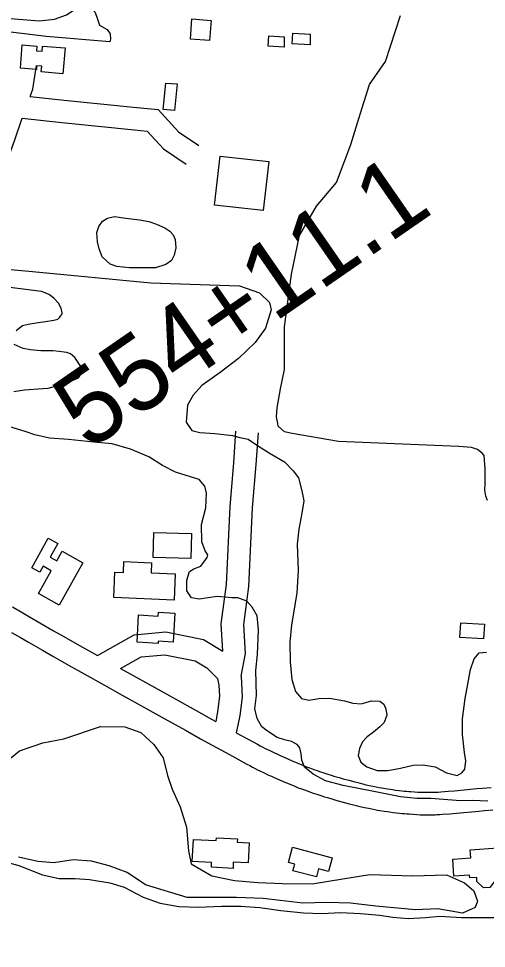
# Model space of a CAD drawing. Extents: x 3715084 to 3753216, y 488173 to 513963.
# Drawn here: x 3736153 to 3736776, y 500239 to 501479 of the extents above; entities that cross this region are included whole.
import ezdxf

# ---------------------------------------------------------------- set-up
doc = ezdxf.new("R2010")
doc.units = 0
for name, color, linetype in [('V-BLDG-OTLN', 7, 'Continuous'), ('V-ROAD-CNTR', 7, 'Continuous'), ('V-SITE-VEGE', 7, 'Continuous'), ('V-SURV-IDEN', 7, 'Continuous'), ('V-TOPO-SHOR', 7, 'Continuous')]:
    doc.layers.add(name, color=color, linetype=linetype)

msp = doc.modelspace()

# ---------------------------------------------------------------- linework, layer by layer
at = {"layer": 'V-BLDG-OTLN'}
for points in [[(3736409.2, 501476.5), (3736407.3, 501449.5), (3736381.7, 501451.3), (3736383.6, 501478.4)], [(3736506.8, 501441), (3736485.4, 501442.2), (3736486.1, 501455.8), (3736506.7, 501454.7)], [(3736541.1, 501443.9), (3736517.3, 501445.1), (3736518, 501459.3), (3736541.4, 501458.1)], [(3736184.7, 501442.3), (3736214.9, 501439.7), (3736212, 501405.3), (3736183.1, 501407.8), (3736183.7, 501415.3), (3736176.9, 501415.9), (3736176.5, 501411.2), (3736155.2, 501413), (3736157.8, 501443.7), (3736177, 501442.1), (3736176.5, 501436.1), (3736184.1, 501435.4)], [(3736364.1, 501391.7), (3736360.6, 501356.4), (3736345.5, 501357.8), (3736349, 501392.9)], [(3736478.8, 501223.1), (3736414, 501230.3), (3736421.2, 501295.5), (3736486, 501288.3)], [(3736333.2, 500793.8), (3736383.4, 500792.5), (3736382.5, 500759.1), (3736332.3, 500760.4)], [(3736238.5, 500753.3), (3736206.9, 500696.6), (3736179.2, 500712.1), (3736196.2, 500742.6), (3736185.5, 500748.6), (3736181.1, 500740.6), (3736170.4, 500746.5), (3736192.4, 500786), (3736205.1, 500778.9), (3736195, 500760.8), (3736203.6, 500756), (3736210.8, 500768.7)], [(3736329.3, 500739.7), (3736361.5, 500738.4), (3736360.1, 500703.6), (3736279.7, 500706.8), (3736281.1, 500740.8), (3736292.6, 500740.3), (3736293.2, 500754.8), (3736329.8, 500753.3)], [(3736360.8, 500686.3), (3736358.9, 500647.6), (3736338.9, 500648.7), (3736338.7, 500645.8), (3736310.6, 500647.2), (3736312.4, 500683.7), (3736339, 500682.3), (3736339.2, 500687.4)], [(3736742, 500673.3), (3736773.5, 500671.3), (3736772.3, 500651.9), (3736740.8, 500653.8)], [(3736460, 500380), (3736458.7, 500353), (3736438.9, 500353.9), (3736438.5, 500345.8), (3736409.7, 500347.2), (3736410, 500353.6), (3736384.3, 500354.9), (3736385.8, 500384.3), (3736416.2, 500382.9), (3736416.4, 500386.6), (3736444.4, 500385.3), (3736444.2, 500380.8)], [(3736517.9, 500374.2), (3736570.7, 500360), (3736565.8, 500341.5), (3736552.5, 500345.1), (3736549.6, 500334.3), (3736518.4, 500342.7), (3736520.7, 500351.3), (3736512.4, 500353.5)], [(3736827.9, 500337.2), (3736787.3, 500334.6), (3736787.6, 500329.5), (3736780.5, 500320.5), (3736772.2, 500319.8), (3736763.5, 500328.4), (3736763.3, 500333.6), (3736754, 500333), (3736753.7, 500336.6), (3736732.6, 500335.2), (3736731.2, 500358.1), (3736755.2, 500359.7), (3736754.5, 500370.7), (3736791.4, 500373), (3736792.1, 500361.4), (3736826.2, 500363.5), (3736826.4, 500360.4), (3736838.4, 500361.2), (3736839.8, 500339.8), (3736827.8, 500339)]]:
    msp.add_lwpolyline(points, close=True, dxfattribs=at)
at = {"layer": 'V-ROAD-CNTR'}
for points in [[(3736168.2, 501375.2), (3736171.8, 501384.7), (3736176.5, 501416.5)], [(3736168.2, 501375.2), (3736213.4, 501370.3), (3736310.5, 501360.5), (3736338.7, 501357.5), (3736365.7, 501328.1), (3736392.9, 501309.6)], [(3736047.3, 501279.8), (3736088, 501278.7), (3736133.7, 501278), (3736148, 501317.2), (3736157.5, 501346.2)], [(3736157.5, 501346.2), (3736210.3, 501340.4), (3736307.4, 501330.7), (3736324.3, 501328.9), (3736346, 501305.2), (3736376.1, 501284.8)], [(3736424.9, 500635.2), (3736422.6, 500671.9), (3736429.7, 500724.4), (3736434.6, 500828.5), (3736439.4, 500886.7), (3736442.4, 500928.7)], [(3736449.3, 500602.1), (3736455.2, 500632.1), (3736452.8, 500670.8), (3736459.6, 500721.7), (3736464.5, 500826.6), (3736469.3, 500884.4), (3736472.4, 500926.5)], [(3736144.8, 500694.4), (3736158.5, 500686.4), (3736170.5, 500679.4), (3736181, 500673.4), (3736199.5, 500662.7), (3736213.3, 500654.8), (3736234.2, 500643), (3736257.8, 500629.7)], [(3736143.4, 500660.5), (3736155.5, 500653.5), (3736166.1, 500647.4), (3736184.6, 500636.7), (3736198.5, 500628.8), (3736219.4, 500616.9), (3736240.3, 500605.1), (3736267.3, 500589.9), (3736290.9, 500576.7), (3736311.6, 500565.1), (3736347.8, 500545), (3736375, 500529.9), (3736395.4, 500518.6), (3736410.7, 500510.1), (3736433.7, 500497.5), (3736456.8, 500484.9), (3736460.7, 500482.8), (3736464.4, 500480.8), (3736467.9, 500479), (3736471.2, 500477.4), (3736474.3, 500475.9), (3736480, 500473.1), (3736485.1, 500470.7), (3736489.6, 500468.6), (3736493.5, 500466.9), (3736500.3, 500463.9), (3736505.5, 500461.7), (3736513.3, 500458.4), (3736521, 500455.2), (3736525.5, 500453.4), (3736529.7, 500451.8), (3736533.6, 500450.4), (3736537.4, 500449), (3736540.8, 500447.8), (3736544.1, 500446.6), (3736550.2, 500444.6), (3736555.6, 500442.9), (3736560.2, 500441.4)], [(3736257.8, 500629.7), (3736307, 500657), (3736349.1, 500661), (3736399, 500651), (3736424.9, 500635.2)], [(3736288.5, 500612.4), (3736316, 500627.8), (3736347.5, 500630.7), (3736387.9, 500622.6), (3736403.5, 500613.1), (3736418, 500599), (3736419.8, 500590.1), (3736420.5, 500575.2), (3736417.9, 500554.4), (3736415.4, 500541.8)], [(3736288.5, 500612.4), (3736305.6, 500602.9), (3736326.2, 500591.3), (3736362.4, 500571.2), (3736389.5, 500556.1), (3736409.9, 500544.9), (3736415.4, 500541.8)], [(3736449.3, 500602.1), (3736450.6, 500574), (3736447.5, 500549.6), (3736444.9, 500536.7), (3736442.8, 500526.7)], [(3736442.8, 500526.7), (3736471.1, 500511.3), (3736474.8, 500509.3), (3736478.2, 500507.5), (3736481.5, 500505.8), (3736484.6, 500504.2), (3736487.4, 500502.8), (3736492.9, 500500.2), (3736497.7, 500497.9), (3736502, 500496), (3736505.7, 500494.3), (3736512.3, 500491.4), (3736517.2, 500489.3), (3736524.7, 500486.1), (3736532.3, 500483), (3736536.4, 500481.4), (3736540.4, 500479.9), (3736544, 500478.5), (3736547.5, 500477.2), (3736550.7, 500476.1), (3736553.8, 500475), (3736559.6, 500473.1), (3736564.6, 500471.5), (3736569.2, 500470)], [(3736569.1, 500470.1), (3736573, 500468.9), (3736579.9, 500466.8), (3736585.1, 500465.3), (3736593, 500463.2), (3736600.9, 500461), (3736604.6, 500460.1), (3736608.1, 500459.2), (3736611.3, 500458.4), (3736614.3, 500457.7), (3736620, 500456.4), (3736624.9, 500455.3), (3736629.3, 500454.4), (3736633.1, 500453.7), (3736636.4, 500453.1), (3736639.3, 500452.6), (3736644.4, 500451.7), (3736648.2, 500451.2), (3736651.1, 500450.8), (3736655.4, 500450.2), (3736659.8, 500449.7), (3736663.3, 500449.3), (3736666.6, 500448.9), (3736669.7, 500448.6), (3736672.6, 500448.4), (3736675.3, 500448.2), (3736680.4, 500447.8), (3736684.8, 500447.6), (3736688.7, 500447.4), (3736692, 500447.3), (3736695, 500447.2), (3736697.5, 500447.2), (3736699.7, 500447.2), (3736703.7, 500447.3), (3736706.6, 500447.4), (3736708.7, 500447.4), (3736712, 500447.6), (3736715.3, 500447.8), (3736724.9, 500448.6), (3736733.4, 500449.4), (3736763.4, 500452.1), (3736770.9, 500452.8), (3736782.2, 500453.8)], [(3736560.3, 500441.4), (3736564.4, 500440.1), (3736571.6, 500438), (3736577, 500436.5), (3736585.1, 500434.2), (3736593.3, 500432), (3736597.2, 500431), (3736600.8, 500430.1), (3736604.2, 500429.3), (3736607.5, 500428.5), (3736613.5, 500427.1), (3736618.8, 500426), (3736623.4, 500425), (3736627.5, 500424.2), (3736631.1, 500423.6), (3736634.2, 500423), (3736639.7, 500422.1), (3736643.9, 500421.5), (3736647, 500421), (3736651.7, 500420.4), (3736656.4, 500419.9), (3736660.2, 500419.4), (3736663.7, 500419.1), (3736667, 500418.8), (3736670.1, 500418.5), (3736673, 500418.3), (3736678.5, 500417.9), (3736683.3, 500417.6), (3736687.6, 500417.4), (3736691.3, 500417.3), (3736694.5, 500417.2), (3736697.4, 500417.2), (3736699.9, 500417.2), (3736704.3, 500417.3), (3736707.6, 500417.4), (3736710.1, 500417.5), (3736713.8, 500417.7), (3736717.5, 500417.9), (3736727.5, 500418.7), (3736736.1, 500419.5), (3736766.1, 500422.2), (3736773.6, 500422.9), (3736784.7, 500423.9)]]:
    msp.add_lwpolyline(points, dxfattribs=at)
msp.add_spline([(3733715.6, 498954.1), (3733927.4, 498985.4), (3734149, 499017.4), (3734317.1, 499039.2), (3734452.5, 499051), (3734616.6, 499062.1), (3734803.5, 499064.4), (3734911.8, 499064.8), (3735132.1, 499070), (3735323.3, 499078.4), (3735505.8, 499097.1), (3735898.1, 499142.6), (3736237.2, 499184.4), (3736547.4, 499225.5), (3736808.2, 499257.6), (3736976.4, 499281.2), (3737080, 499296.5), (3737176, 499320.7), (3737240, 499343.3), (3737319.4, 499377.9), (3737388.9, 499415.8), (3737461.6, 499455.9), (3737533.7, 499510.1), (3737613.7, 499584.1), (3737686.3, 499661.4), (3737745.2, 499744.2), (3737793.2, 499828.8), (3737831, 499907.6), (3737863.3, 499993.7), (3737884.5, 500070), (3737902, 500150.4), (3737918.8, 500240.6), (3737947.8, 500405.1), (3737975.6, 500525.4)], degree=3, dxfattribs=at)
at = {"layer": 'V-SITE-VEGE'}
msp.add_lwpolyline([(3736033.3, 501474.3), (3736029.3, 501474.9), (3736026.4, 501475.4), (3736022.3, 501479.5), (3736020.6, 501483), (3736021.7, 501487.6), (3736028.1, 501489.9), (3736097.8, 501482.4), (3736180.2, 501476), (3736200.5, 501478.3), (3736216.7, 501484.1), (3736229.5, 501492.2), (3736239.4, 501494.5), (3736248.1, 501494.5), (3736254.4, 501488.1), (3736256.8, 501482.3), (3736260.8, 501470.1), (3736270.7, 501464.3), (3736274.7, 501458.5), (3736275.3, 501451.6), (3736274.2, 501448.1), (3736189.4, 501455.1)], close=True, dxfattribs=at)
for points in [[(3736777.4, 500836.2), (3736775.1, 500842.1), (3736773.9, 500850.3), (3736774.5, 500859.1), (3736774.5, 500878.5), (3736773.3, 500896.1), (3736770.4, 500899.6), (3736764, 500904.3), (3736756.3, 500907.2), (3736739.3, 500908.4), (3736579.1, 500914.9), (3736517.5, 500925.5), (3736506.9, 500927.9), (3736498.7, 500935.5), (3736498.1, 500939), (3736496.3, 500947.8), (3736497.5, 500960.1), (3736501.6, 500985.4), (3736506.9, 501011), (3736506.9, 501068), (3736516.6, 501138.1), (3736526.9, 501189.6), (3736549.6, 501228.7), (3736576.4, 501260.3), (3736595.6, 501311.2), (3736605.9, 501345.5), (3736620.4, 501390.8), (3736641.7, 501421.8), (3736661.6, 501482.9)], [(3736024.5, 501155.1), (3736171.3, 501141.7), (3736329.2, 501126.6), (3736447, 501122.5), (3736473.7, 501113.2), (3736487, 501100.4), (3736489.3, 501090.5), (3736481.8, 501066.2), (3736467.8, 501047), (3736445.8, 501025.6), (3736421.4, 501007), (3736397, 500989.6), (3736385.4, 500976.8), (3736377.8, 500963.5), (3736376.1, 500940.9), (3736383.6, 500929.8), (3736394.1, 500926.9), (3736414.4, 500925.8)], [(3736149.8, 501062.8), (3736158, 501069.8), (3736165.5, 501071.5), (3736178.8, 501073.8), (3736188.7, 501075), (3736199.7, 501076.7), (3736205, 501077.9), (3736207.9, 501080.8), (3736210.8, 501085.4), (3736210.8, 501086.6), (3736209.6, 501093), (3736206.1, 501099.3), (3736199.8, 501106.3), (3736193.9, 501110.4), (3736188.1, 501113.3), (3736183.5, 501115), (3736137.7, 501120.8)], [(3736146.3, 500981.6), (3736160.8, 500983.9), (3736178.8, 500985), (3736192.2, 500986.2), (3736216.5, 500992.6), (3736232.8, 501000.1), (3736237.4, 501007.1), (3736237.4, 501012.3), (3736227.6, 501026.8), (3736221.8, 501032), (3736217.1, 501033.8), (3736213.7, 501034.3), (3736206.7, 501034.9), (3736198.6, 501036.1), (3736182.3, 501036.1), (3736168.4, 501037.3), (3736159.1, 501039), (3736146.9, 501044.2)], [(3736497.2, 500520.1), (3736484.5, 500528.8), (3736476.9, 500534.6), (3736470.5, 500545.6), (3736467.6, 500558.4), (3736470, 500576.4), (3736468.8, 500609.5), (3736471.2, 500630.9), (3736472.3, 500664), (3736470.6, 500682.6), (3736464.2, 500694.2), (3736456.7, 500702.3), (3736445.1, 500706.4), (3736436.9, 500706.4), (3736417.2, 500708.1), (3736393.4, 500704.7), (3736383, 500706.4), (3736377.2, 500715.7), (3736377.2, 500730.2), (3736380.7, 500741.8), (3736386.5, 500745.3), (3736395.8, 500748.8), (3736403.9, 500760.4), (3736405, 500763.9), (3736401.6, 500769.1), (3736396.9, 500781.3), (3736396.4, 500804.5), (3736402.2, 500826.5), (3736403.3, 500846.3), (3736401, 500855.5), (3736393.5, 500864.2), (3736381.9, 500867.7), (3736362.1, 500874.1), (3736344.7, 500882.8), (3736326.2, 500894.4), (3736301.8, 500904.9), (3736277.4, 500911.9), (3736253.1, 500914.2), (3736219.4, 500917.7), (3736193.9, 500919.5), (3736174.7, 500924.1), (3736161.4, 500928.2), (3736141.1, 500934.6)], [(3736414.4, 500925.8), (3736437.6, 500922.8), (3736447.5, 500920.5), (3736458.5, 500918.2), (3736472.4, 500908.9), (3736488.1, 500899), (3736507.2, 500888), (3736518.8, 500875.8), (3736525.8, 500866.5), (3736530.4, 500849.1), (3736532.7, 500835.8), (3736530.4, 500819.5), (3736526.3, 500798), (3736524, 500778.3), (3736525.2, 500742.9), (3736523.4, 500712.7), (3736516.4, 500670.4), (3736514.1, 500647.2), (3736514.7, 500621.1), (3736517, 500597.8), (3736521.6, 500581.6), (3736529.7, 500572.3), (3736539.6, 500570), (3736553, 500572.3), (3736566.9, 500572.9), (3736587.2, 500569.4), (3736598.2, 500565.9), (3736609.2, 500565.3), (3736615.6, 500567.1), (3736623.2, 500569.4), (3736634.2, 500568.8), (3736639.4, 500564.7), (3736642.3, 500558.3), (3736643.5, 500550.2), (3736640, 500540.4), (3736634.2, 500534.6), (3736625.5, 500527.6), (3736617.3, 500521.2), (3736611, 500514.3), (3736606.9, 500505.6), (3736605.2, 500496.3), (3736608.6, 500487.6), (3736616.8, 500481.2), (3736630.7, 500476.5), (3736644.6, 500476.5), (3736661.4, 500479.4), (3736678.3, 500483.5), (3736691.6, 500484), (3736707.9, 500481.1), (3736722.9, 500473), (3736736.9, 500469.5), (3736743.3, 500473), (3736747.3, 500478.2), (3736748.5, 500489.3), (3736746.7, 500500.3), (3736744.4, 500524.1), (3736744.4, 500545), (3736747.9, 500572.2), (3736751.4, 500591.4), (3736754.9, 500611.1), (3736759.6, 500625), (3736766.5, 500633.2), (3736776.4, 500634.3)], [(3736132.3, 500484.6), (3736154.1, 500502.4), (3736185, 500513.3), (3736213.1, 500518.4), (3736261.9, 500535.1), (3736294.6, 500534.5), (3736315.8, 500527), (3736333, 500510.9), (3736345.6, 500493.2), (3736351.3, 500469.7), (3736357.6, 500451.3), (3736367.9, 500427.8), (3736376.5, 500400.8), (3736379.4, 500369.3), (3736382.6, 500351.8), (3736410.3, 500336), (3736440.7, 500329.7), (3736472.2, 500326.8), (3736504.3, 500325.7), (3736543.9, 500325.1), (3736584.6, 500332), (3736620.7, 500337.7), (3736678.1, 500335.9), (3736722.8, 500337.1), (3736746.9, 500326.7), (3736759.5, 500315.8), (3736764.1, 500302.1), (3736761.2, 500293.5), (3736744, 500286), (3736711.3, 500291.8), (3736681.5, 500290.6), (3736628.8, 500295.2), (3736594.9, 500299.3), (3736563.4, 500300.4), (3736531.3, 500299.3), (3736478.5, 500305.6), (3736443, 500306.8), (3736410.9, 500306.8), (3736377.6, 500306.8), (3736322, 500324), (3736297.4, 500340.1), (3736273.3, 500349.3), (3736249.8, 500355.6), (3736225.7, 500357.3), (3736199.9, 500353.3), (3736178.7, 500355), (3736152.9, 500360.8)], [(3736778.1, 500435.3), (3736757.7, 500436.4), (3736741.5, 500435.9), (3736702, 500438.8), (3736683.5, 500438.8), (3736661.4, 500441.1), (3736626, 500448.1), (3736585.4, 500456.2), (3736561.6, 500462.6), (3736545.4, 500471.3), (3736533.8, 500480.6), (3736530.3, 500489.9), (3736529.1, 500498.6), (3736527.4, 500506.7), (3736523.9, 500510.8), (3736516.4, 500514.9), (3736507.1, 500517.2), (3736497.2, 500520.1)]]:
    msp.add_lwpolyline(points, dxfattribs=at)
at = {"layer": 'V-TOPO-SHOR'}
for points in [[(3736295.8, 501212.7), (3736314.1, 501210.6), (3736326.2, 501208.5), (3736336.7, 501204.8), (3736347.7, 501200.1), (3736354.5, 501195.3), (3736358.7, 501190.6), (3736361.3, 501184.3), (3736362.3, 501173.3), (3736360.2, 501163.4), (3736356.6, 501156.5), (3736349.2, 501150.8), (3736335.1, 501146.6), (3736318.3, 501146.6), (3736300.5, 501146.6), (3736283.7, 501148.2), (3736274.8, 501151.3), (3736264.3, 501161.3), (3736260.1, 501171.8), (3736258, 501181.2), (3736257, 501193.8), (3736259.6, 501201.7), (3736264.8, 501209), (3736271.1, 501212.7), (3736280.6, 501214.8), (3736295.8, 501212.7)], [(3736117.1, 500359.3), (3736153.1, 500349.8), (3736184.7, 500337.2), (3736206.8, 500332.1), (3736228.3, 500332.1), (3736247.3, 500330.8), (3736274.5, 500326.4), (3736293.4, 500320.7), (3736318.7, 500307.4), (3736341.5, 500299.2), (3736366.1, 500294.8), (3736392.7, 500294.1), (3736423, 500295.4), (3736448.9, 500295.4), (3736474.2, 500293.5), (3736502, 500289.7), (3736532.3, 500286.5), (3736557, 500285.8), (3736581.7, 500287.1), (3736608.2, 500285.8), (3736633.5, 500283.3), (3736651.2, 500280.8), (3736672, 500278.8), (3736694.8, 500280.1), (3736713.8, 500282), (3736742.8, 500280.1), (3736769.4, 500280.1), (3736820, 500280.1)]]:
    msp.add_lwpolyline(points, dxfattribs=at)

# ---------------------------------------------------------------- texts
at = {"layer": 'V-SURV-IDEN'}
msp.add_text('554+11.1', height=100, rotation=34.678, dxfattribs=at).set_placement((3736245.8, 500901.7))

doc.saveas('drawing.dxf')
